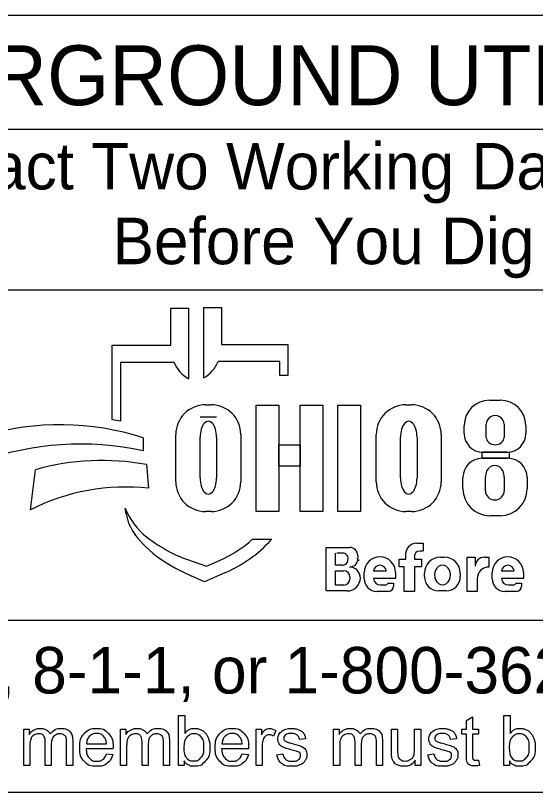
# Model space of a CAD drawing. Extents: x 0 to 45.9, y 0 to 22.
# Drawn here: x 26.446 to 28.01, y 4.439 to 6.776 of the extents above; entities that cross this region are included whole.
import ezdxf

# ---------------------------------------------------------------- set-up
doc = ezdxf.new("R2010")
doc.units = 0
doc.layers.add('SH_Border', color=7, linetype='Continuous')
doc.layers.add('SH_Cut_Line', color=7, linetype='Continuous')

msp = doc.modelspace()

# ---------------------------------------------------------------- linework, layer by layer
at = {"layer": 'SH_Border'}
for p, q in [((26.9125, 5.7842), (26.9125, 5.8957)), ((26.9125, 5.8957), (26.9661, 5.8957)), ((26.9661, 5.8957), (26.9661, 5.6836)), ((27.0118, 5.6859), (27.0118, 5.898)), ((27.0118, 5.898), (27.0654, 5.898)), ((27.0654, 5.898), (27.0654, 5.7865)), ((26.7365, 5.5603), (26.7365, 5.7842)), ((26.7365, 5.7842), (26.9125, 5.7842)), ((27.0654, 5.7865), (27.2647, 5.7865)), ((27.2647, 5.7865), (27.2647, 5.6927)), ((26.7617, 5.7327), (26.7617, 5.5559)), ((26.9229, 5.7327), (26.7617, 5.7327)), ((27.2414, 5.7351), (27.055, 5.7351)), ((27.2414, 5.6927), (27.2414, 5.7351)), ((27.2647, 5.6927), (27.2414, 5.6927)), ((27.872, 5.619), (27.9048, 5.619)), ((27.0175, 5.605), (27.034, 5.605)), ((27.6205, 5.605), (27.637, 5.605)), ((27.0507, 5.568), (27.0009, 5.568)), ((27.7957, 5.5184), (27.7957, 5.5427)), ((27.8619, 5.507), (27.8619, 5.5463)), ((27.916, 5.5463), (27.916, 5.507)), ((27.9811, 5.5427), (27.9811, 5.5184)), ((26.8298, 5.5056), (26.8298, 5.4668)), ((26.928, 5.3735), (26.928, 5.5155)), ((27.0009, 5.3849), (27.0009, 5.5073)), ((27.0507, 5.5073), (27.0507, 5.3849)), ((27.1235, 5.5155), (27.1235, 5.3735)), ((27.531, 5.3735), (27.531, 5.5155)), ((27.6039, 5.3849), (27.6039, 5.5073)), ((27.6537, 5.5073), (27.6537, 5.3849)), ((27.7265, 5.5155), (27.7265, 5.3735)), ((27.9251, 5.4624), (27.8517, 5.4624)), ((26.8398, 5.425), (26.846, 5.3541)), ((27.8499, 5.4441), (27.9272, 5.4441)), ((26.491, 5.2895), (26.5056, 5.4096)), ((27.792, 5.3522), (27.792, 5.3862)), ((27.8595, 5.3462), (27.8595, 5.3871)), ((27.9164, 5.3871), (27.9164, 5.3462)), ((27.9851, 5.3862), (27.9851, 5.3522)), ((26.7787, 5.2766), (26.7756, 5.2945)), ((27.034, 5.2841), (27.0175, 5.2841)), ((27.637, 5.2841), (27.6205, 5.2841)), ((27.9042, 5.2712), (27.873, 5.2712)), ((27.1589, 5.2007), (27.2164, 5.2007)), ((27.3802, 5.0449), (27.3802, 5.1757)), ((27.3802, 5.1757), (27.4514, 5.1757)), ((27.6528, 5.1885), (27.6723, 5.1885)), ((27.6723, 5.1885), (27.6723, 5.1655)), ((27.4082, 5.1222), (27.4082, 5.1591)), ((27.4334, 5.1591), (27.4121, 5.1591)), ((27.4752, 5.1519), (27.4752, 5.144)), ((27.6196, 5.1401), (27.6196, 5.1505)), ((27.6457, 5.1485), (27.6457, 5.1401)), ((27.6723, 5.165), (27.6621, 5.165)), ((27.724, 5.1467), (27.7362, 5.1467)), ((27.8043, 5.0437), (27.8043, 5.1464)), ((27.8043, 5.1464), (27.8288, 5.1464)), ((27.8288, 5.1464), (27.8288, 5.1195)), ((27.8561, 5.1464), (27.87, 5.1464)), ((27.87, 5.1464), (27.87, 5.1168)), ((26.9605, 5.1403), (27.0199, 5.1198)), ((27.0199, 5.1198), (27.061, 5.1376)), ((27.4276, 5.1222), (27.4082, 5.1222)), ((27.6002, 5.1171), (27.6002, 5.1401)), ((27.6002, 5.1401), (27.6196, 5.1401)), ((27.6457, 5.1401), (27.6672, 5.1401)), ((27.6672, 5.1401), (27.6672, 5.1171)), ((27.0772, 5.1003), (27.0139, 5.0728)), ((27.4082, 5.0628), (27.4082, 5.1056)), ((27.4082, 5.1056), (27.4337, 5.1056)), ((27.4948, 5.0817), (27.4948, 5.1001)), ((27.5614, 5.1041), (27.5228, 5.1041)), ((27.5893, 5.1001), (27.5893, 5.0825)), ((27.6151, 5.1171), (27.6002, 5.1171)), ((27.6151, 5.0437), (27.6151, 5.1171)), ((27.6672, 5.1171), (27.6457, 5.1171)), ((27.6457, 5.1171), (27.6457, 5.0437)), ((27.6762, 5.088), (27.6762, 5.0988)), ((27.784, 5.0988), (27.784, 5.088)), ((27.8797, 5.0817), (27.8797, 5.1001)), ((27.9463, 5.1041), (27.9078, 5.1041)), ((27.9742, 5.1001), (27.9742, 5.0825)), ((27.0139, 5.0728), (26.9766, 5.0893)), ((27.4519, 5.0875), (27.4519, 5.0811)), ((27.4832, 5.0846), (27.4832, 5.0843)), ((27.5893, 5.0825), (27.5229, 5.0825)), ((27.8348, 5.0819), (27.8348, 5.0437)), ((27.9742, 5.0825), (27.9078, 5.0825)), ((27.4335, 5.0628), (27.4082, 5.0628)), ((27.5438, 5.0632), (27.5579, 5.0632)), ((27.5665, 5.0688), (27.5834, 5.0688)), ((27.5834, 5.0688), (27.5834, 5.059)), ((27.9287, 5.0632), (27.9429, 5.0632)), ((27.9514, 5.0688), (27.9683, 5.0688)), ((27.9683, 5.0688), (27.9683, 5.059)), ((27.4439, 5.0449), (27.3802, 5.0449)), ((27.5681, 5.0437), (27.5328, 5.0437)), ((27.6457, 5.0437), (27.6151, 5.0437)), ((27.7412, 5.0453), (27.719, 5.0453)), ((27.8348, 5.0437), (27.8043, 5.0437)), ((27.9531, 5.0437), (27.9177, 5.0437))]:
    msp.add_line(p, q, dxfattribs=at)
for points in [[(27.1699, 5.604), (27.2378, 5.604), (27.2378, 5.284), (27.1699, 5.284)], [(27.302, 5.604), (27.37, 5.604), (27.37, 5.284), (27.302, 5.284)], [(27.4153, 5.604), (27.4841, 5.604), (27.4841, 5.284), (27.4153, 5.284)], [(27.2378, 5.4841), (27.302, 5.4841), (27.302, 5.4201), (27.2378, 5.4201)], [(27.8496, 5.4624), (27.9312, 5.4624), (27.9312, 5.444), (27.8496, 5.444)]]:
    msp.add_lwpolyline(points, close=True, dxfattribs=at)
for points in [[(26.9532, 4.5198), (26.9362, 4.5198), (26.9362, 4.67), (26.9546, 4.67), (26.9546, 4.6165)], [(27.8022, 4.5517), (27.8022, 4.6143), (27.7886, 4.6143), (27.7886, 4.6287), (27.8022, 4.6287), (27.8022, 4.6556), (27.8206, 4.6667), (27.8206, 4.6287), (27.839, 4.6287), (27.839, 4.6143), (27.8206, 4.6143), (27.8206, 4.5506)], [(27.9323, 4.5198), (27.9153, 4.5198), (27.9153, 4.67), (27.9337, 4.67), (27.9337, 4.6165)], [(26.4702, 4.5198), (26.4702, 4.6287), (26.4866, 4.6287), (26.4866, 4.6133)], [(26.7615, 4.5198), (26.7615, 4.6287), (26.778, 4.6287), (26.778, 4.6133)], [(27.1693, 4.5198), (27.1693, 4.6287), (27.1859, 4.6287), (27.1859, 4.6122)], [(27.4025, 4.5198), (27.4025, 4.6287), (27.419, 4.6287), (27.419, 4.6133)], [(27.5768, 4.5613), (27.5768, 4.6287), (27.5953, 4.6287), (27.5953, 4.5683)], [(27.6465, 4.5704), (27.6465, 4.6287), (27.665, 4.6287), (27.665, 4.5198), (27.6485, 4.5198)], [(27.2284, 4.6252), (27.2219, 4.6081)], [(26.5532, 4.583), (26.5532, 4.5198), (26.5348, 4.5198), (26.5348, 4.5905)], [(26.6177, 4.5945), (26.6177, 4.5198), (26.5993, 4.5198), (26.5993, 4.5883)], [(26.6588, 4.5846), (26.7196, 4.5846)], [(26.8446, 4.583), (26.8446, 4.5198), (26.8262, 4.5198), (26.8262, 4.5905)], [(26.9091, 4.5945), (26.9091, 4.5198), (26.8906, 4.5198), (26.8906, 4.5883)], [(27.0668, 4.5846), (27.1275, 4.5846)], [(27.3183, 4.6005), (27.3002, 4.5981)], [(27.4856, 4.583), (27.4856, 4.5198), (27.4672, 4.5198), (27.4672, 4.5905)], [(27.55, 4.5945), (27.55, 4.5198), (27.5316, 4.5198), (27.5316, 4.5883)], [(27.7729, 4.6005), (27.7548, 4.5981)], [(26.4886, 4.5762), (26.4886, 4.5198), (26.4702, 4.5198)], [(26.7389, 4.5695), (26.6578, 4.5695)], [(26.78, 4.5762), (26.78, 4.5198), (26.7615, 4.5198)], [(27.1469, 4.5695), (27.0657, 4.5695)], [(27.1877, 4.5768), (27.1877, 4.5198), (27.1693, 4.5198)], [(27.421, 4.5762), (27.421, 4.5198), (27.4025, 4.5198)], [(26.7193, 4.5549), (26.7384, 4.5525)], [(27.1273, 4.5549), (27.1464, 4.5525)], [(27.2319, 4.5523), (27.2501, 4.5552)], [(27.6485, 4.5198), (27.6485, 4.5359)], [(27.6865, 4.5523), (27.7047, 4.5552)], [(27.839, 4.5362), (27.8417, 4.52)], [(26.9532, 4.5334), (26.9532, 4.5198)], [(27.9323, 4.5334), (27.9323, 4.5198)]]:
    msp.add_lwpolyline(points, dxfattribs=at)
for centre, radius, start, end in [((27.0142, 5.7695), 0.0985, 201.9296, 240.7469), ((26.9637, 5.7718), 0.0985, 299.2531, 338.0704), ((27.872, 5.5427), 0.0763, 90, 180), ((27.9048, 5.5427), 0.0763, 0, 90), ((27.0175, 5.5155), 0.0895, 90, 180), ((27.034, 5.5155), 0.0895, 0, 90), ((27.6205, 5.5155), 0.0895, 90, 180), ((27.637, 5.5155), 0.0895, 0, 90), ((26.5786, 4.726), 0.8191, 72.1402, 106.3144), ((26.6084, 4.7513), 0.8191, 79.2074, 81.0007), ((27.8517, 5.5184), 0.056, 180, 270), ((27.9251, 5.5184), 0.056, 270, 0), ((26.6417, 4.5949), 0.8919, 77.8238, 109.8274), ((26.7056, 4.7053), 0.7322, 79.44, 105.8467), ((27.8499, 5.3862), 0.0579, 90, 180), ((27.9272, 5.3862), 0.0579, 0, 90), ((26.7776, 4.722), 0.6357, 83.8248, 116.8021), ((27.0175, 5.3735), 0.0895, 180, 270), ((27.034, 5.3735), 0.0895, 270, 0), ((27.6205, 5.3735), 0.0895, 180, 270), ((27.637, 5.3735), 0.0895, 270, 0), ((27.873, 5.3522), 0.081, 180, 270), ((27.9042, 5.3522), 0.081, 270, 0), ((26.963, 5.3666), 0.2008, 201.0457, 232.5314), ((26.92, 5.3007), 0.1433, 189.6817, 216.0884), ((27.0536, 5.3981), 0.3088, 216.0884, 235.7167), ((27.1555, 5.6178), 0.5173, 232.5314, 241.794), ((26.9176, 5.4681), 0.3602, 293.4582, 312.0712), ((26.9176, 5.4681), 0.401, 293.4582, 317.8286), ((27.4514, 5.1519), 0.0238, 0, 90), ((27.6528, 5.1549), 0.0335, 90, 187.5187), ((27.2201, 5.6424), 0.6044, 235.7167, 246.2325), ((27.0704, 5.459), 0.3371, 241.794, 250.9821), ((27.4295, 5.1422), 0.0169, 357.8325, 90), ((27.451, 5.1412), 0.0243, 270, 6.6529), ((27.542, 5.1001), 0.0473, 0, 180), ((27.6621, 5.1485), 0.0165, 90, 180), ((27.724, 5.0988), 0.0478, 90, 180), ((27.7362, 5.0988), 0.0478, 0, 90), ((27.8557, 5.1195), 0.0269, 89.2449, 180), ((27.927, 5.1001), 0.0473, 0, 180), ((27.4276, 5.1409), 0.0187, 270, 2.0582), ((27.4616, 5.1397), 0.0175, 347.4023, 0), ((27.5421, 5.1031), 0.0193, 2.9632, 177.0368), ((27.927, 5.1031), 0.0193, 2.9632, 177.0368), ((27.4337, 5.0875), 0.0181, 0, 90), ((27.4511, 5.0848), 0.0321, 4.0748, 90), ((27.8697, 5.0819), 0.0349, 89.6033, 180), ((27.4335, 5.0811), 0.0184, 270, 0), ((27.4439, 5.0843), 0.0393, 270, 0), ((27.4503, 5.0846), 0.033, 0, 11.7502), ((27.5328, 5.0817), 0.038, 180, 270), ((27.5438, 5.0842), 0.021, 184.827, 270), ((27.719, 5.088), 0.0428, 180, 270), ((27.7412, 5.088), 0.0428, 270, 0), ((27.9177, 5.0817), 0.038, 180, 270), ((27.9287, 5.0842), 0.021, 184.827, 270), ((27.5579, 5.0726), 0.00938, 270, 335.9979), ((27.5681, 5.059), 0.0152, 270, 0), ((27.9429, 5.0726), 0.00938, 270, 335.9979), ((27.9531, 5.059), 0.0152, 270, 0)]:
    msp.add_arc(centre, radius, start, end, dxfattribs=at)
for centre, major_axis, ratio, start_param, end_param in [((27.8889, 5.5463), (0.0271, 0), 0.969373, 0, 3.141593), ((27.0258, 5.5073), (0, 0.0484), 0.514403, 4.712389, 7.853982), ((27.6288, 5.5073), (0, 0.0484), 0.514403, 4.712389, 7.853982), ((27.8889, 5.507), (0.0271, 0), 0.818453, 3.141593, 6.283185), ((27.8879, 5.3871), (0, 0.0358), 0.794529, 4.712389, 7.853982), ((27.0258, 5.3849), (0, 0.0484), 0.514403, 1.570796, 4.712389), ((27.6288, 5.3849), (0, 0.0484), 0.514403, 1.570796, 4.712389), ((27.8879, 5.3462), (0.0284, 0), 0.959837, 3.141593, 6.283185), ((27.7306, 5.0934), (0, 0.029), 0.832186, 4.712389, 7.853982), ((27.7306, 5.0934), (0, 0.0302), 0.797287, 1.570796, 4.712389)]:
    msp.add_ellipse(centre, major_axis=major_axis, ratio=ratio, start_param=start_param, end_param=end_param, dxfattribs=at)
for points in [[(26.4866, 4.6133), (26.4918, 4.6213), (26.5003, 4.6262), (26.5088, 4.6311), (26.5196, 4.6311), (26.5317, 4.6311), (26.5395, 4.626), (26.5472, 4.621), (26.5504, 4.612), (26.5633, 4.6311), (26.584, 4.6311), (26.6002, 4.6311), (26.609, 4.6221), (26.6177, 4.6131), (26.6177, 4.5945)], [(26.7384, 4.5525), (26.7339, 4.5359), (26.7217, 4.5266), (26.7095, 4.5174), (26.6906, 4.5174), (26.6667, 4.5174), (26.6527, 4.5321), (26.6388, 4.5468), (26.6388, 4.5733), (26.6388, 4.6008), (26.6529, 4.6159), (26.667, 4.6311), (26.6895, 4.6311), (26.7114, 4.6311), (26.7252, 4.6162), (26.739, 4.6013), (26.739, 4.5744), (26.739, 4.5728), (26.7389, 4.5695)], [(26.778, 4.6133), (26.7831, 4.6213), (26.7916, 4.6262), (26.8001, 4.6311), (26.811, 4.6311), (26.8231, 4.6311), (26.8308, 4.626), (26.8386, 4.621), (26.8418, 4.612), (26.8547, 4.6311), (26.8754, 4.6311), (26.8916, 4.6311), (26.9003, 4.6221), (26.9091, 4.6131), (26.9091, 4.5945)], [(26.9546, 4.6165), (26.9663, 4.6311), (26.9844, 4.6311), (26.9945, 4.6311), (27.0034, 4.627), (27.0124, 4.623), (27.0182, 4.6156), (27.0239, 4.6083), (27.0272, 4.598), (27.0305, 4.5876), (27.0305, 4.5759), (27.0305, 4.5479), (27.0167, 4.5327), (27.0028, 4.5174), (26.9835, 4.5174), (26.9642, 4.5174), (26.9532, 4.5334)], [(27.1464, 4.5525), (27.1419, 4.5359), (27.1297, 4.5266), (27.1175, 4.5174), (27.0986, 4.5174), (27.0747, 4.5174), (27.0607, 4.5321), (27.0467, 4.5468), (27.0467, 4.5733), (27.0467, 4.6008), (27.0609, 4.6159), (27.075, 4.6311), (27.0975, 4.6311), (27.1193, 4.6311), (27.1332, 4.6162), (27.147, 4.6013), (27.147, 4.5744), (27.147, 4.5728), (27.1469, 4.5695)], [(27.1859, 4.6122), (27.1923, 4.6237), (27.1976, 4.6274), (27.203, 4.6311), (27.2094, 4.6311), (27.2188, 4.6311), (27.2284, 4.6252)], [(27.2501, 4.5552), (27.2517, 4.5442), (27.2587, 4.5384), (27.2657, 4.5325), (27.2784, 4.5325), (27.2911, 4.5325), (27.2973, 4.5377), (27.3034, 4.5429), (27.3034, 4.5499), (27.3034, 4.5561), (27.298, 4.5597), (27.2942, 4.5622), (27.2791, 4.566), (27.2588, 4.5711), (27.251, 4.5748), (27.2431, 4.5786), (27.2391, 4.5852), (27.235, 4.5918), (27.235, 4.5997), (27.235, 4.607), (27.2383, 4.6132), (27.2417, 4.6194), (27.2474, 4.6235), (27.2517, 4.6267), (27.2592, 4.6289), (27.2666, 4.6311), (27.2751, 4.6311), (27.288, 4.6311), (27.2976, 4.6274), (27.3073, 4.6237), (27.312, 4.6174), (27.3166, 4.6111), (27.3183, 4.6005)], [(27.419, 4.6133), (27.4241, 4.6213), (27.4326, 4.6262), (27.4411, 4.6311), (27.452, 4.6311), (27.4641, 4.6311), (27.4718, 4.626), (27.4796, 4.621), (27.4828, 4.612), (27.4957, 4.6311), (27.5164, 4.6311), (27.5326, 4.6311), (27.5413, 4.6221), (27.55, 4.6131), (27.55, 4.5945)], [(27.7047, 4.5552), (27.7062, 4.5442), (27.7133, 4.5384), (27.7203, 4.5325), (27.7329, 4.5325), (27.7457, 4.5325), (27.7518, 4.5377), (27.758, 4.5429), (27.758, 4.5499), (27.758, 4.5561), (27.7526, 4.5597), (27.7488, 4.5622), (27.7337, 4.566), (27.7134, 4.5711), (27.7055, 4.5748), (27.6977, 4.5786), (27.6936, 4.5852), (27.6896, 4.5918), (27.6896, 4.5997), (27.6896, 4.607), (27.6929, 4.6132), (27.6962, 4.6194), (27.702, 4.6235), (27.7063, 4.6267), (27.7137, 4.6289), (27.7212, 4.6311), (27.7297, 4.6311), (27.7425, 4.6311), (27.7522, 4.6274), (27.7619, 4.6237), (27.7665, 4.6174), (27.7711, 4.6111), (27.7729, 4.6005)], [(27.9337, 4.6165), (27.9454, 4.6311), (27.9635, 4.6311), (27.9735, 4.6311), (27.9825, 4.627), (27.9914, 4.623), (27.9972, 4.6156), (28.003, 4.6083), (28.0063, 4.598), (28.0096, 4.5876), (28.0096, 4.5759), (28.0096, 4.5479), (27.9957, 4.5327), (27.9819, 4.5174), (27.9625, 4.5174), (27.9433, 4.5174), (27.9323, 4.5334)], [(26.5348, 4.5905), (26.5348, 4.6027), (26.5303, 4.6089), (26.5258, 4.615), (26.5155, 4.615), (26.5078, 4.615), (26.5011, 4.6109), (26.4945, 4.6068), (26.4916, 4.599), (26.4886, 4.5911), (26.4886, 4.5762)], [(26.5993, 4.5883), (26.5993, 4.5994), (26.5975, 4.6042), (26.5957, 4.6091), (26.591, 4.6121), (26.5862, 4.615), (26.5799, 4.615), (26.5684, 4.615), (26.5608, 4.6074), (26.5532, 4.5998), (26.5532, 4.583)], [(26.7196, 4.5846), (26.7183, 4.5984), (26.7126, 4.6053), (26.7038, 4.6159), (26.6897, 4.6159), (26.677, 4.6159), (26.6684, 4.6074), (26.6597, 4.5989), (26.6588, 4.5846)], [(26.8262, 4.5905), (26.8262, 4.6027), (26.8217, 4.6089), (26.8172, 4.615), (26.8069, 4.615), (26.7991, 4.615), (26.7925, 4.6109), (26.7859, 4.6068), (26.7829, 4.599), (26.78, 4.5911), (26.78, 4.5762)], [(26.8906, 4.5883), (26.8906, 4.5994), (26.8888, 4.6042), (26.887, 4.6091), (26.8823, 4.6121), (26.8776, 4.615), (26.8713, 4.615), (26.8598, 4.615), (26.8522, 4.6074), (26.8446, 4.5998), (26.8446, 4.583)], [(26.953, 4.5751), (26.953, 4.5555), (26.9583, 4.5468), (26.967, 4.5325), (26.9818, 4.5325), (26.9939, 4.5325), (27.0027, 4.543), (27.0115, 4.5535), (27.0115, 4.5743), (27.0115, 4.5957), (27.0031, 4.6058), (26.9946, 4.6159), (26.9827, 4.6159), (26.9706, 4.6159), (26.9618, 4.6054), (26.953, 4.5949), (26.953, 4.5751)], [(27.1275, 4.5846), (27.1263, 4.5984), (27.1206, 4.6053), (27.1118, 4.6159), (27.0977, 4.6159), (27.085, 4.6159), (27.0764, 4.6074), (27.0677, 4.5989), (27.0668, 4.5846)], [(27.2219, 4.6081), (27.2152, 4.6121), (27.2085, 4.6121), (27.2024, 4.6121), (27.1976, 4.6084), (27.1929, 4.6048), (27.1908, 4.5983), (27.1877, 4.5885), (27.1877, 4.5768)], [(27.3002, 4.5981), (27.299, 4.6065), (27.2931, 4.6112), (27.2872, 4.6159), (27.2764, 4.6159), (27.2637, 4.6159), (27.2583, 4.6117), (27.2529, 4.6075), (27.2529, 4.6019), (27.2529, 4.5983), (27.2551, 4.5954), (27.2574, 4.5925), (27.2622, 4.5905), (27.265, 4.5895), (27.2785, 4.5858), (27.2981, 4.5806), (27.3058, 4.5772), (27.3136, 4.5739), (27.318, 4.5676), (27.3224, 4.5612), (27.3224, 4.5518), (27.3224, 4.5426), (27.3171, 4.5345), (27.3117, 4.5263), (27.3015, 4.5219), (27.2913, 4.5174), (27.2785, 4.5174), (27.2573, 4.5174), (27.2461, 4.5262), (27.235, 4.535), (27.2319, 4.5523)], [(27.4672, 4.5905), (27.4672, 4.6027), (27.4627, 4.6089), (27.4582, 4.615), (27.4479, 4.615), (27.4401, 4.615), (27.4335, 4.6109), (27.4269, 4.6068), (27.4239, 4.599), (27.421, 4.5911), (27.421, 4.5762)], [(27.5316, 4.5883), (27.5316, 4.5994), (27.5298, 4.6042), (27.528, 4.6091), (27.5233, 4.6121), (27.5186, 4.615), (27.5123, 4.615), (27.5008, 4.615), (27.4932, 4.6074), (27.4856, 4.5998), (27.4856, 4.583)], [(27.7548, 4.5981), (27.7536, 4.6065), (27.7477, 4.6112), (27.7418, 4.6159), (27.731, 4.6159), (27.7183, 4.6159), (27.7129, 4.6117), (27.7074, 4.6075), (27.7074, 4.6019), (27.7074, 4.5983), (27.7097, 4.5954), (27.7119, 4.5925), (27.7168, 4.5905), (27.7195, 4.5895), (27.7331, 4.5858), (27.7527, 4.5806), (27.7604, 4.5772), (27.7682, 4.5739), (27.7726, 4.5676), (27.777, 4.5612), (27.777, 4.5518), (27.777, 4.5426), (27.7716, 4.5345), (27.7662, 4.5263), (27.7561, 4.5219), (27.7459, 4.5174), (27.7331, 4.5174), (27.7118, 4.5174), (27.7007, 4.5262), (27.6896, 4.535), (27.6865, 4.5523)], [(27.9321, 4.5751), (27.9321, 4.5555), (27.9374, 4.5468), (27.9461, 4.5325), (27.9609, 4.5325), (27.973, 4.5325), (27.9818, 4.543), (27.9906, 4.5535), (27.9906, 4.5743), (27.9906, 4.5957), (27.9821, 4.6058), (27.9737, 4.6159), (27.9617, 4.6159), (27.9497, 4.6159), (27.9409, 4.6054), (27.9321, 4.5949), (27.9321, 4.5751)], [(26.6578, 4.5695), (26.6588, 4.5516), (26.6679, 4.542), (26.677, 4.5325), (26.6906, 4.5325), (26.7008, 4.5325), (26.708, 4.5379), (26.7151, 4.5432), (26.7193, 4.5549)], [(27.0657, 4.5695), (27.0668, 4.5516), (27.0759, 4.542), (27.085, 4.5325), (27.0986, 4.5325), (27.1088, 4.5325), (27.116, 4.5379), (27.1231, 4.5432), (27.1273, 4.5549)], [(27.6485, 4.5359), (27.6358, 4.5174), (27.614, 4.5174), (27.6044, 4.5174), (27.596, 4.5211), (27.5877, 4.5248), (27.5837, 4.5304), (27.5796, 4.536), (27.578, 4.544), (27.5768, 4.5495), (27.5768, 4.5613)], [(27.5953, 4.5683), (27.5953, 4.5539), (27.5964, 4.5489), (27.5981, 4.5416), (27.6038, 4.5375), (27.6094, 4.5333), (27.6177, 4.5333), (27.626, 4.5333), (27.6332, 4.5376), (27.6405, 4.5418), (27.6435, 4.5491), (27.6465, 4.5565), (27.6465, 4.5704)], [(27.8417, 4.52), (27.8339, 4.5183), (27.8278, 4.5183), (27.8177, 4.5183), (27.8122, 4.5215), (27.8067, 4.5247), (27.8044, 4.5299), (27.8022, 4.535), (27.8022, 4.5517)], [(27.8206, 4.5506), (27.8206, 4.5427), (27.8216, 4.5404), (27.8225, 4.5382), (27.8247, 4.5368), (27.8269, 4.5355), (27.831, 4.5355), (27.8341, 4.5355), (27.839, 4.5362)]]:
    msp.add_open_spline(points, degree=3, dxfattribs=at)
at = {"layer": 'SH_Cut_Line'}
for p, q in [((29.8064, 6.7762), (25.5564, 6.7762)), ((25.5564, 6.4346), (29.8064, 6.4346)), ((25.5564, 5.9512), (29.8064, 5.9512)), ((29.8064, 4.9565), (25.5564, 4.9565)), ((29.8064, 4.4387), (25.5564, 4.4387))]:
    msp.add_line(p, q, dxfattribs=at)

# ---------------------------------------------------------------- texts
at = {"layer": 'SH_Border'}
for s, height, p in [('UNDERGROUND UTILITIES', 0.18, (25.6846, 6.5065)), ('Contact Two Working Days', 0.14, (25.9761, 6.253)), ('Before You Dig', 0.14, (26.7373, 6.028)), ('OHIO811, 8-1-1, or 1-800-362-2764', 0.14, (25.6009, 4.7365))]:
    msp.add_text(s, height=height, dxfattribs=at).set_placement(p)

doc.saveas('drawing.dxf')
